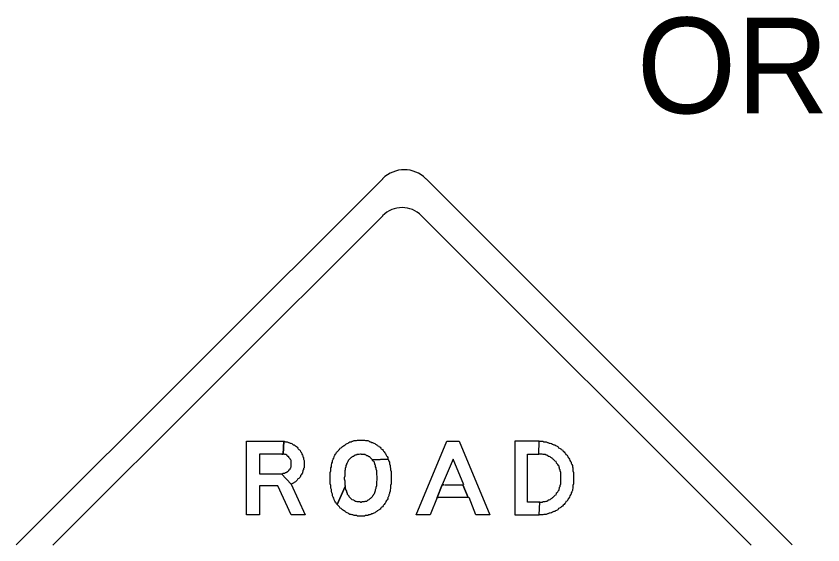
# Model space of a CAD drawing. Extents: x 1342 to 1558, y 178 to 457.
# Drawn here: x 1451.15 to 1464.22, y 215.58 to 224.15 of the extents above; entities that cross this region are included whole.
import ezdxf

# ---------------------------------------------------------------- set-up
doc = ezdxf.new("R2010")
doc.units = 0
for name, color, linetype in [('Level 1', 7, 'Continuous'), ('Level 10', 7, 'Continuous'), ('Level 44', 7, 'Continuous')]:
    doc.layers.add(name, color=color, linetype=linetype)

msp = doc.modelspace()

# ---------------------------------------------------------------- linework, layer by layer
at = {"layer": 'Level 1'}
for p, q in [((1455.461, 217.262), (1455.49, 217.262)), ((1455.49, 217.262), (1455.481, 217.055)), ((1455.481, 217.055), (1455.49, 217.262)), ((1459.619, 217.055), (1459.628, 217.262)), ((1459.619, 217.055), (1459.628, 217.262)), ((1455.461, 217.055), (1455.481, 217.055)), ((1456.929, 216.959), (1457.183, 216.971)), ((1457.183, 216.971), (1456.929, 216.959)), ((1455.452, 216.735), (1455.612, 216.566)), ((1455.612, 216.566), (1455.452, 216.735)), ((1456.355, 216.237), (1456.487, 216.528)), ((1456.487, 216.528), (1456.355, 216.237)), ((1457.973, 216.35), (1458.058, 216.557)), ((1458.058, 216.557), (1457.973, 216.35)), ((1458.058, 216.557), (1458.078, 216.557)), ((1458.392, 216.557), (1458.474, 216.35)), ((1458.474, 216.35), (1458.392, 216.557)), ((1457.973, 216.35), (1457.989, 216.35)), ((1459.628, 216.068), (1459.637, 216.275)), ((1459.637, 216.275), (1459.628, 216.275)), ((1459.628, 216.068), (1459.637, 216.275)), ((1454.888, 216.068), (1454.888, 216.068)), ((1457.634, 216.068), (1457.634, 216.068)), ((1459.233, 216.068), (1459.233, 216.068))]:
    msp.add_line(p, q, dxfattribs=at)
for points in [[(1455.612, 216.566), (1455.838, 216.068), (1455.612, 216.068), (1455.396, 216.538), (1455.095, 216.538), (1455.095, 216.068), (1454.888, 216.068), (1454.888, 217.262), (1455.461, 217.262)], [(1455.452, 217.262), (1455.471, 217.262), (1455.49, 217.262), (1455.499, 217.262), (1455.518, 217.253), (1455.537, 217.253), (1455.546, 217.253), (1455.565, 217.244), (1455.574, 217.244), (1455.593, 217.234), (1455.602, 217.234), (1455.622, 217.224), (1455.631, 217.215), (1455.64, 217.206), (1455.659, 217.206), (1455.668, 217.196), (1455.678, 217.187), (1455.697, 217.178), (1455.706, 217.168), (1455.716, 217.149), (1455.725, 217.14), (1455.734, 217.13), (1455.743, 217.121), (1455.753, 217.112), (1455.763, 217.093), (1455.772, 217.083), (1455.781, 217.065), (1455.781, 217.055), (1455.791, 217.037), (1455.8, 217.027), (1455.8, 217.008), (1455.809, 216.999), (1455.809, 216.98), (1455.809, 216.971), (1455.819, 216.951), (1455.819, 216.942), (1455.819, 216.924), (1455.819, 216.905), (1455.819, 216.896), (1455.819, 216.876), (1455.819, 216.867), (1455.819, 216.848), (1455.819, 216.83), (1455.809, 216.82), (1455.809, 216.801), (1455.8, 216.792), (1455.8, 216.773), (1455.791, 216.764), (1455.791, 216.744), (1455.781, 216.735), (1455.772, 216.717), (1455.763, 216.707), (1455.763, 216.698), (1455.753, 216.679), (1455.743, 216.669), (1455.734, 216.66), (1455.716, 216.651), (1455.706, 216.632), (1455.697, 216.623), (1455.688, 216.613), (1455.678, 216.603), (1455.659, 216.594), (1455.65, 216.585), (1455.64, 216.585), (1455.622, 216.575), (1455.612, 216.566)], [(1456.355, 216.237), (1456.346, 216.246), (1456.336, 216.265), (1456.327, 216.275), (1456.318, 216.293), (1456.308, 216.312), (1456.308, 216.321), (1456.299, 216.341), (1456.289, 216.359), (1456.28, 216.378), (1456.28, 216.406), (1456.271, 216.425), (1456.261, 216.453), (1456.261, 216.482), (1456.252, 216.5), (1456.252, 216.528), (1456.252, 216.548), (1456.243, 216.575), (1456.243, 216.603), (1456.243, 216.623), (1456.243, 216.651), (1456.243, 216.679), (1456.243, 216.707), (1456.243, 216.726), (1456.243, 216.754), (1456.252, 216.782), (1456.252, 216.801), (1456.252, 216.83), (1456.261, 216.848), (1456.261, 216.876), (1456.271, 216.905), (1456.28, 216.924), (1456.28, 216.951), (1456.289, 216.971), (1456.299, 216.989), (1456.308, 217.008), (1456.308, 217.017), (1456.318, 217.037), (1456.327, 217.055), (1456.336, 217.065), (1456.346, 217.083), (1456.355, 217.093), (1456.374, 217.112), (1456.384, 217.121), (1456.393, 217.13), (1456.402, 217.149), (1456.421, 217.158), (1456.43, 217.168), (1456.44, 217.178), (1456.459, 217.187), (1456.468, 217.196), (1456.487, 217.206), (1456.496, 217.215), (1456.515, 217.224), (1456.534, 217.234), (1456.543, 217.244), (1456.562, 217.253), (1456.581, 217.253), (1456.6, 217.262), (1456.609, 217.262), (1456.628, 217.272), (1456.647, 217.272), (1456.666, 217.272), (1456.684, 217.281), (1456.694, 217.281), (1456.712, 217.281), (1456.731, 217.281), (1456.75, 217.281), (1456.769, 217.281), (1456.788, 217.281), (1456.797, 217.281), (1456.816, 217.272), (1456.835, 217.272), (1456.854, 217.272), (1456.872, 217.262), (1456.882, 217.253), (1456.901, 217.253), (1456.919, 217.244), (1456.929, 217.244), (1456.948, 217.234), (1456.966, 217.224), (1456.976, 217.215), (1456.995, 217.206), (1457.004, 217.196), (1457.023, 217.187), (1457.032, 217.178), (1457.051, 217.168), (1457.06, 217.149), (1457.07, 217.14), (1457.089, 217.13), (1457.098, 217.112), (1457.107, 217.103), (1457.117, 217.093), (1457.126, 217.074), (1457.136, 217.065), (1457.145, 217.046), (1457.155, 217.027), (1457.164, 217.017), (1457.173, 216.999), (1457.173, 216.98), (1457.183, 216.971)], [(1457.634, 216.068), (1458.133, 217.262), (1458.33, 217.262), (1458.829, 216.068), (1458.603, 216.068), (1458.491, 216.349)], [(1459.628, 217.262), (1459.233, 217.262), (1459.233, 216.068), (1459.628, 216.068)], [(1459.628, 217.262), (1459.647, 217.262), (1459.666, 217.262), (1459.685, 217.262), (1459.703, 217.253), (1459.722, 217.253), (1459.741, 217.253), (1459.76, 217.244), (1459.769, 217.244), (1459.788, 217.234), (1459.807, 217.234), (1459.826, 217.224), (1459.844, 217.215), (1459.864, 217.206), (1459.882, 217.206), (1459.891, 217.196), (1459.91, 217.187), (1459.929, 217.178), (1459.939, 217.158), (1459.957, 217.149), (1459.976, 217.14), (1459.985, 217.13), (1460.005, 217.121), (1460.014, 217.103), (1460.033, 217.093), (1460.042, 217.074), (1460.051, 217.065), (1460.061, 217.046), (1460.08, 217.037), (1460.089, 217.017), (1460.098, 216.999), (1460.108, 216.989), (1460.117, 216.971), (1460.126, 216.951), (1460.136, 216.933), (1460.146, 216.924), (1460.146, 216.905), (1460.155, 216.886), (1460.164, 216.867), (1460.164, 216.848), (1460.174, 216.83), (1460.174, 216.801), (1460.174, 216.782), (1460.183, 216.754), (1460.183, 216.735), (1460.183, 216.707), (1460.183, 216.689), (1460.183, 216.669), (1460.183, 216.641), (1460.183, 216.623), (1460.183, 216.594), (1460.183, 216.575), (1460.174, 216.548), (1460.174, 216.528), (1460.174, 216.5), (1460.164, 216.482)], [(1455.461, 217.055), (1455.095, 217.055), (1455.095, 216.735), (1455.461, 216.735)], [(1455.452, 216.735), (1455.471, 216.735), (1455.481, 216.744), (1455.49, 216.744), (1455.499, 216.744), (1455.509, 216.744), (1455.518, 216.754), (1455.527, 216.754), (1455.537, 216.764), (1455.546, 216.764), (1455.546, 216.773), (1455.556, 216.773), (1455.565, 216.782), (1455.574, 216.792), (1455.574, 216.801), (1455.584, 216.801), (1455.593, 216.81), (1455.593, 216.82), (1455.602, 216.83), (1455.602, 216.839), (1455.612, 216.848), (1455.612, 216.858), (1455.612, 216.867), (1455.612, 216.876), (1455.612, 216.886), (1455.612, 216.896), (1455.612, 216.905), (1455.612, 216.914), (1455.612, 216.924), (1455.612, 216.933), (1455.612, 216.951), (1455.602, 216.961), (1455.593, 216.971), (1455.593, 216.98), (1455.584, 216.989), (1455.574, 216.999), (1455.574, 217.008), (1455.565, 217.017), (1455.556, 217.017), (1455.546, 217.027), (1455.546, 217.037), (1455.537, 217.037), (1455.527, 217.046), (1455.518, 217.046), (1455.509, 217.046), (1455.499, 217.055), (1455.49, 217.055), (1455.481, 217.055), (1455.471, 217.055), (1455.461, 217.055)], [(1456.926, 216.964), (1456.919, 216.971), (1456.91, 216.98), (1456.901, 216.989), (1456.891, 216.999), (1456.882, 217.008), (1456.872, 217.008), (1456.863, 217.017), (1456.844, 217.027), (1456.835, 217.027), (1456.825, 217.037), (1456.816, 217.037), (1456.807, 217.046), (1456.788, 217.046), (1456.778, 217.046), (1456.769, 217.046), (1456.75, 217.046), (1456.741, 217.055), (1456.731, 217.055), (1456.712, 217.046), (1456.703, 217.046), (1456.694, 217.046), (1456.675, 217.046), (1456.666, 217.037), (1456.656, 217.037)], [(1459.628, 216.275), (1459.44, 216.275), (1459.44, 217.055), (1459.619, 217.055)], [(1459.967, 216.801), (1459.957, 216.81), (1459.957, 216.83), (1459.948, 216.839), (1459.948, 216.858), (1459.939, 216.867), (1459.929, 216.886), (1459.919, 216.896), (1459.91, 216.905), (1459.91, 216.914), (1459.901, 216.933), (1459.882, 216.942), (1459.873, 216.951), (1459.864, 216.961), (1459.854, 216.971), (1459.844, 216.98), (1459.835, 216.989), (1459.816, 216.999), (1459.807, 217.008), (1459.788, 217.017), (1459.778, 217.017), (1459.769, 217.027), (1459.75, 217.037), (1459.741, 217.037), (1459.722, 217.046), (1459.712, 217.046), (1459.694, 217.046), (1459.675, 217.055), (1459.666, 217.055), (1459.647, 217.055), (1459.637, 217.055), (1459.619, 217.055)], [(1457.183, 216.971), (1457.192, 216.942), (1457.201, 216.924), (1457.201, 216.896), (1457.211, 216.867), (1457.211, 216.848), (1457.221, 216.82), (1457.221, 216.801), (1457.23, 216.773), (1457.23, 216.744), (1457.23, 216.726), (1457.23, 216.698), (1457.23, 216.669), (1457.23, 216.651), (1457.23, 216.623), (1457.23, 216.603), (1457.23, 216.575), (1457.221, 216.548), (1457.221, 216.528), (1457.221, 216.5), (1457.211, 216.472), (1457.211, 216.453), (1457.201, 216.425), (1457.201, 216.416), (1457.192, 216.397), (1457.192, 216.378), (1457.183, 216.359), (1457.173, 216.35), (1457.173, 216.331), (1457.164, 216.312), (1457.155, 216.303), (1457.145, 216.284), (1457.136, 216.265), (1457.126, 216.256), (1457.117, 216.237), (1457.107, 216.227), (1457.098, 216.218), (1457.089, 216.199), (1457.07, 216.19), (1457.06, 216.18), (1457.051, 216.162), (1457.032, 216.152), (1457.023, 216.143), (1457.004, 216.134), (1456.995, 216.124), (1456.976, 216.115), (1456.966, 216.105), (1456.948, 216.096), (1456.929, 216.086), (1456.919, 216.086), (1456.901, 216.077), (1456.882, 216.068), (1456.863, 216.068), (1456.854, 216.058), (1456.835, 216.058), (1456.816, 216.058), (1456.797, 216.049), (1456.778, 216.049), (1456.769, 216.049), (1456.75, 216.049), (1456.731, 216.049), (1456.712, 216.049), (1456.694, 216.049), (1456.684, 216.049), (1456.666, 216.058), (1456.647, 216.058), (1456.628, 216.058), (1456.609, 216.068), (1456.6, 216.068), (1456.581, 216.077), (1456.562, 216.077), (1456.543, 216.086), (1456.534, 216.096), (1456.515, 216.105), (1456.496, 216.115), (1456.487, 216.124), (1456.468, 216.134), (1456.459, 216.143), (1456.44, 216.152), (1456.43, 216.162), (1456.421, 216.171), (1456.402, 216.18), (1456.393, 216.199), (1456.384, 216.209), (1456.374, 216.218), (1456.355, 216.237)], [(1456.656, 217.037), (1456.647, 217.037), (1456.628, 217.027), (1456.619, 217.017), (1456.609, 217.017), (1456.6, 217.008), (1456.59, 216.999), (1456.581, 216.999), (1456.571, 216.989), (1456.562, 216.98), (1456.553, 216.971), (1456.543, 216.961), (1456.534, 216.951), (1456.534, 216.942), (1456.525, 216.933), (1456.515, 216.914), (1456.515, 216.905), (1456.505, 216.896), (1456.505, 216.886), (1456.496, 216.867), (1456.496, 216.858), (1456.496, 216.848), (1456.487, 216.82), (1456.487, 216.801), (1456.478, 216.782), (1456.478, 216.764), (1456.478, 216.735), (1456.478, 216.717), (1456.478, 216.698), (1456.468, 216.669), (1456.468, 216.651), (1456.478, 216.623), (1456.478, 216.603), (1456.478, 216.585), (1456.478, 216.557), (1456.487, 216.538), (1456.487, 216.528)], [(1456.505, 216.434), (1456.515, 216.425), (1456.515, 216.406), (1456.525, 216.397), (1456.534, 216.387), (1456.543, 216.378), (1456.543, 216.368), (1456.553, 216.359), (1456.562, 216.35), (1456.571, 216.341), (1456.581, 216.331), (1456.59, 216.321), (1456.6, 216.321), (1456.619, 216.312), (1456.628, 216.303), (1456.637, 216.303), (1456.647, 216.293), (1456.656, 216.293), (1456.675, 216.284), (1456.684, 216.284), (1456.694, 216.284), (1456.712, 216.284), (1456.722, 216.284), (1456.731, 216.275), (1456.75, 216.275), (1456.76, 216.284), (1456.769, 216.284), (1456.788, 216.284), (1456.797, 216.284), (1456.807, 216.293), (1456.816, 216.293), (1456.835, 216.293), (1456.844, 216.303), (1456.854, 216.312), (1456.863, 216.312), (1456.872, 216.321), (1456.882, 216.331), (1456.891, 216.341), (1456.901, 216.341), (1456.91, 216.35), (1456.919, 216.359), (1456.929, 216.368), (1456.938, 216.387), (1456.948, 216.397), (1456.948, 216.406), (1456.957, 216.416), (1456.966, 216.425), (1456.966, 216.434), (1456.976, 216.462), (1456.976, 216.482), (1456.985, 216.5), (1456.985, 216.519), (1456.995, 216.548), (1456.995, 216.566), (1456.995, 216.585), (1456.995, 216.613), (1457.004, 216.632), (1457.004, 216.651), (1457.004, 216.679), (1457.004, 216.698), (1456.995, 216.717), (1456.995, 216.744), (1456.995, 216.764), (1456.995, 216.782), (1456.985, 216.81), (1456.985, 216.83), (1456.976, 216.848), (1456.976, 216.867), (1456.976, 216.876), (1456.966, 216.886), (1456.966, 216.896), (1456.957, 216.914), (1456.957, 216.924), (1456.948, 216.933), (1456.938, 216.942), (1456.929, 216.951), (1456.929, 216.959)], [(1458.406, 216.557), (1458.236, 216.971), (1458.058, 216.557)], [(1459.967, 216.528), (1459.967, 216.548), (1459.976, 216.575), (1459.976, 216.594), (1459.976, 216.613), (1459.976, 216.632), (1459.976, 216.651), (1459.976, 216.679), (1459.976, 216.698), (1459.976, 216.717), (1459.976, 216.735), (1459.976, 216.754), (1459.967, 216.782), (1459.967, 216.801)], [(1456.487, 216.522), (1456.487, 216.519), (1456.487, 216.5), (1456.496, 216.472), (1456.505, 216.453), (1456.505, 216.434)], [(1458.075, 216.557), (1458.058, 216.557)], [(1458.082, 216.557), (1458.078, 216.557)], [(1458.091, 216.557), (1458.392, 216.557)], [(1459.619, 216.275), (1459.637, 216.275), (1459.647, 216.275), (1459.666, 216.275), (1459.675, 216.275), (1459.694, 216.284), (1459.712, 216.284), (1459.722, 216.284), (1459.741, 216.293), (1459.75, 216.293), (1459.769, 216.303), (1459.778, 216.312), (1459.788, 216.312), (1459.807, 216.321), (1459.816, 216.331), (1459.835, 216.341), (1459.844, 216.35), (1459.854, 216.359), (1459.864, 216.368), (1459.873, 216.378), (1459.882, 216.387), (1459.901, 216.397), (1459.91, 216.416), (1459.91, 216.425), (1459.919, 216.434), (1459.929, 216.444), (1459.939, 216.462), (1459.948, 216.472), (1459.948, 216.491), (1459.957, 216.5), (1459.957, 216.519), (1459.967, 216.528)], [(1460.164, 216.482), (1460.164, 216.462), (1460.155, 216.444), (1460.146, 216.425), (1460.146, 216.406), (1460.136, 216.397), (1460.126, 216.378), (1460.117, 216.359), (1460.108, 216.341), (1460.098, 216.331), (1460.089, 216.312), (1460.08, 216.293), (1460.061, 216.284), (1460.051, 216.265), (1460.042, 216.256), (1460.033, 216.237), (1460.014, 216.227), (1460.005, 216.209), (1459.985, 216.199), (1459.976, 216.19), (1459.957, 216.18), (1459.939, 216.171), (1459.929, 216.152), (1459.91, 216.143), (1459.891, 216.134), (1459.882, 216.124), (1459.864, 216.124), (1459.844, 216.115), (1459.826, 216.105), (1459.807, 216.096), (1459.788, 216.096), (1459.769, 216.086), (1459.76, 216.086), (1459.741, 216.077), (1459.722, 216.077), (1459.703, 216.077), (1459.685, 216.068), (1459.666, 216.068), (1459.647, 216.068), (1459.628, 216.068)], [(1457.973, 216.35), (1457.86, 216.068), (1457.634, 216.068)], [(1457.98, 216.35), (1457.973, 216.35)], [(1458.474, 216.35), (1457.989, 216.35)]]:
    msp.add_lwpolyline(points, dxfattribs=at)
at = {"layer": 'Level 44'}
for p, q in [((1457.093, 221.513), (1451.155, 215.585)), ((1463.724, 215.585), (1457.794, 221.513)), ((1451.748, 215.58), (1457.093, 220.916)), ((1457.723, 220.916), (1463.06, 215.58))]:
    msp.add_line(p, q, dxfattribs=at)
for centre, radius in [((1457.442, 221.164), 0.497), ((1457.407, 220.601), 0.447)]:
    msp.add_arc(centre, radius, 45, 135, dxfattribs=at)

# ---------------------------------------------------------------- texts
at = {"layer": 'Level 10'}
msp.add_text('OR', height=1.551, dxfattribs=at).set_placement((1461.207, 222.576))

doc.saveas('drawing.dxf')
